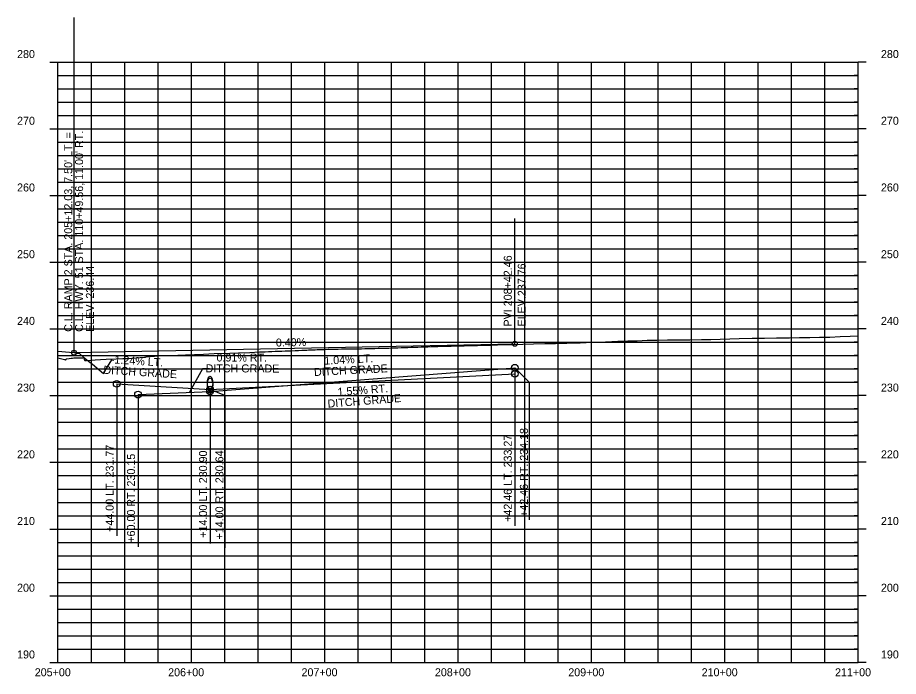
# Model space of a CAD drawing. Extents: x 921603 to 924670, y 1759276 to 1766491.
# Drawn here: x 921610 to 922270, y 1762922 to 1763416 of the extents above; entities that cross this region are included whole.
import ezdxf

# ---------------------------------------------------------------- set-up
doc = ezdxf.new("R2010")
doc.units = 0
for name, color, linetype in [('63', 7, 'Continuous'), ('R_Axis_Annotation', 7, 'Continuous'), ('R_Draft', 7, 'Continuous'), ('R_Exist Surface', 7, 'Continuous'), ('R_Grid', 7, 'Continuous'), ('R_Grid Annot', 7, 'Continuous'), ('R_Grid_Minor', 7, 'Continuous'), ('R_Prop Surface', 7, 'Continuous'), ('R_Proposed Road', 7, 'Continuous'), ('R_Vert Alg', 7, 'Continuous'), ('R_Vert Alg Annot', 7, 'Continuous')]:
    doc.layers.add(name, color=color, linetype=linetype)

msp = doc.modelspace()

# ---------------------------------------------------------------- linework, layer by layer
at = {"layer": 'R_Draft'}
for centre in [(921753.83, 1763141.76), (921753.83, 1763140.46)]:
    msp.add_ellipse(centre, major_axis=(0, 5), ratio=0.4, dxfattribs=at)
at = {"layer": 'R_Exist Surface'}
msp.add_lwpolyline([(921639.83, 1763160.51), (921644.68, 1763159.33), (921645, 1763159.26), (921645.36, 1763159.19), (921645.65, 1763158.97), (921645.88, 1763159.34), (921645.95, 1763159.56), (921646.19, 1763159.88), (921646.28, 1763159.86), (921648.22, 1763160.09), (921649.72, 1763160.32), (921650.62, 1763160.36), (921651.8, 1763160.56), (921658.49, 1763160.49), (921659.04, 1763160.74), (921659.23, 1763160.68), (921659.76, 1763158.74), (921659.84, 1763158.55), (921660.72, 1763158.53), (921661.09, 1763158.55), (921667.79, 1763159.02), (921671.63, 1763159.29), (921675.92, 1763159.58), (921683.41, 1763159.86), (921688.44, 1763160.05), (921692, 1763160.17), (921704.74, 1763161.12), (921705.45, 1763161.19), (921706, 1763161.3), (921715.1, 1763161.98), (921729.56, 1763162.47), (921735.45, 1763162.81), (921748.81, 1763163.25), (921756.86, 1763163.84), (921768.7, 1763164.13), (921775.08, 1763164.43), (921783.58, 1763164.69), (921790.8, 1763165.04), (921795.27, 1763165.18), (921797.75, 1763165.26), (921798.46, 1763165.28), (921800.24, 1763165.36), (921802.73, 1763165.47), (921805.21, 1763165.59), (921806.27, 1763165.64), (921807.7, 1763165.68), (921810.19, 1763165.77), (921812.44, 1763165.85), (921812.67, 1763165.86), (921815.16, 1763165.94), (921817.65, 1763166.03), (921818.25, 1763166.05), (921820.13, 1763166.13), (921822.62, 1763166.24), (921825.1, 1763166.35), (921826.45, 1763166.41), (921827.59, 1763166.46), (921830.08, 1763166.57), (921832.56, 1763166.68), (921834.21, 1763166.75), (921835.05, 1763166.77), (921837.54, 1763166.83), (921840.02, 1763166.89), (921842.51, 1763166.95), (921844.85, 1763167), (921845, 1763167), (921847.48, 1763167.1), (921849.97, 1763167.19), (921852.45, 1763167.29), (921852.7, 1763167.29), (921854.94, 1763167.31), (921857.43, 1763167.32), (921859.91, 1763167.33), (921861.85, 1763167.33), (921862.4, 1763167.35), (921864.89, 1763167.39), (921867.37, 1763167.44), (921869.86, 1763167.48), (921872.35, 1763167.51), (921874.79, 1763167.55), (921874.83, 1763167.55), (921877.32, 1763167.63), (921879.81, 1763167.7), (921882.29, 1763167.78), (921884.78, 1763167.85), (921887.26, 1763167.91), (921888, 1763167.93), (921889.75, 1763167.99), (921892.24, 1763168.07), (921894.72, 1763168.15), (921897.21, 1763168.23), (921898.58, 1763168.27), (921899.7, 1763168.31), (921902.18, 1763168.4), (921904.67, 1763168.48), (921907.16, 1763168.56), (921907.85, 1763168.58), (921909.64, 1763168.66), (921912.13, 1763168.76), (921914.62, 1763168.85), (921914.75, 1763168.86), (921917.1, 1763168.94), (921919.59, 1763169.03), (921921.55, 1763169.1), (921922.07, 1763169.12), (921924.56, 1763169.17), (921927.05, 1763169.23), (921929.53, 1763169.28), (921930.95, 1763169.31), (921932.02, 1763169.35), (921934.51, 1763169.41), (921936.99, 1763169.48), (921939.48, 1763169.55), (921939.65, 1763169.55), (921941.97, 1763169.61), (921944.45, 1763169.68), (921946.6, 1763169.73), (921946.94, 1763169.74), (921949.42, 1763169.8), (921951.91, 1763169.86), (921953.51, 1763169.89), (921954.4, 1763169.91), (921956.88, 1763169.95), (921959.37, 1763170), (921961.86, 1763170.04), (921962.23, 1763170.04), (921964.34, 1763170.12), (921966.83, 1763170.2), (921968.8, 1763170.26), (921969.32, 1763170.28), (921975.23, 1763170.46), (921981.58, 1763170.66), (921988.23, 1763170.87), (921996.22, 1763171.04), (922004.84, 1763171.22), (922012.81, 1763171.4), (922021.44, 1763171.57), (922031.34, 1763171.86), (922040.44, 1763172.26), (922050.25, 1763172.54), (922059.45, 1763172.95), (922067.05, 1763173.27), (922074.08, 1763173.42), (922081.61, 1763173.74), (922088.71, 1763173.88), (922096.81, 1763173.95), (922105.46, 1763174.05), (922113.6, 1763174.12), (922122.2, 1763174.22), (922129.31, 1763174.39), (922136.39, 1763174.67), (922143.55, 1763174.84), (922150.58, 1763175.13), (922160.28, 1763175.2), (922169.42, 1763175.4), (922178.47, 1763175.59), (922188.27, 1763175.66), (922195.65, 1763175.92), (922203.41, 1763175.92), (922210.78, 1763176.18), (922218.55, 1763176.17), (922226.2, 1763176.57), (922233.87, 1763176.74), (922239.83, 1763177.04)], dxfattribs=at)
at = {"layer": 'R_Grid'}
for p, q in [((921639.83, 1762932.26), (921639.83, 1763382.26)), ((921639.83, 1763382.26), (922239.83, 1763382.26)), ((921639.83, 1763382.26), (922239.83, 1763382.26)), ((921739.83, 1762932.26), (921739.83, 1763382.26)), ((921839.83, 1762932.26), (921839.83, 1763382.26)), ((921939.83, 1762932.26), (921939.83, 1763382.26)), ((922039.83, 1762932.26), (922039.83, 1763382.26)), ((922139.83, 1762932.26), (922139.83, 1763382.26)), ((922239.83, 1762932.26), (922239.83, 1763382.26)), ((921639.83, 1763332.26), (922239.83, 1763332.26)), ((921639.83, 1763282.26), (922239.83, 1763282.26)), ((921639.83, 1763232.26), (922239.83, 1763232.26)), ((921639.83, 1763182.26), (922239.83, 1763182.26)), ((921639.83, 1763132.26), (922239.83, 1763132.26)), ((921639.83, 1763082.26), (922239.83, 1763082.26)), ((921639.83, 1763032.26), (922239.83, 1763032.26)), ((921639.83, 1762982.26), (922239.83, 1762982.26)), ((921639.83, 1762932.26), (922239.83, 1762932.26))]:
    msp.add_line(p, q, dxfattribs=at)
at = {"layer": 'R_Grid Annot'}
for p, q in [((921633.83, 1763382.26), (921639.83, 1763382.26)), ((921633.83, 1763382.26), (921639.83, 1763382.26)), ((922245.83, 1763382.26), (922239.83, 1763382.26)), ((922245.83, 1763382.26), (922239.83, 1763382.26)), ((921639.83, 1763372.26), (921642.83, 1763372.26)), ((922239.83, 1763372.26), (922236.83, 1763372.26)), ((921639.83, 1763362.26), (921642.83, 1763362.26)), ((922239.83, 1763362.26), (922236.83, 1763362.26)), ((921639.83, 1763352.26), (921642.83, 1763352.26)), ((922239.83, 1763352.26), (922236.83, 1763352.26)), ((921639.83, 1763342.26), (921642.83, 1763342.26)), ((922239.83, 1763342.26), (922236.83, 1763342.26)), ((921633.83, 1763332.26), (921639.83, 1763332.26)), ((922245.83, 1763332.26), (922239.83, 1763332.26)), ((921639.83, 1763322.26), (921642.83, 1763322.26)), ((922239.83, 1763322.26), (922236.83, 1763322.26)), ((921639.83, 1763312.26), (921642.83, 1763312.26)), ((922239.83, 1763312.26), (922236.83, 1763312.26)), ((921639.83, 1763302.26), (921642.83, 1763302.26)), ((922239.83, 1763302.26), (922236.83, 1763302.26)), ((921639.83, 1763292.26), (921642.83, 1763292.26)), ((922239.83, 1763292.26), (922236.83, 1763292.26)), ((921633.83, 1763282.26), (921639.83, 1763282.26)), ((922245.83, 1763282.26), (922239.83, 1763282.26)), ((921639.83, 1763272.26), (921642.83, 1763272.26)), ((922239.83, 1763272.26), (922236.83, 1763272.26)), ((921639.83, 1763262.26), (921642.83, 1763262.26)), ((922239.83, 1763262.26), (922236.83, 1763262.26)), ((921639.83, 1763252.26), (921642.83, 1763252.26)), ((922239.83, 1763252.26), (922236.83, 1763252.26)), ((921639.83, 1763242.26), (921642.83, 1763242.26)), ((922239.83, 1763242.26), (922236.83, 1763242.26)), ((921633.83, 1763232.26), (921639.83, 1763232.26)), ((922245.83, 1763232.26), (922239.83, 1763232.26)), ((921639.83, 1763222.26), (921642.83, 1763222.26)), ((922239.83, 1763222.26), (922236.83, 1763222.26)), ((921639.83, 1763212.26), (921642.83, 1763212.26)), ((922239.83, 1763212.26), (922236.83, 1763212.26)), ((921639.83, 1763202.26), (921642.83, 1763202.26)), ((922239.83, 1763202.26), (922236.83, 1763202.26)), ((921639.83, 1763192.26), (921642.83, 1763192.26)), ((922239.83, 1763192.26), (922236.83, 1763192.26)), ((921633.83, 1763182.26), (921639.83, 1763182.26)), ((922245.83, 1763182.26), (922239.83, 1763182.26)), ((921639.83, 1763172.26), (921642.83, 1763172.26)), ((922239.83, 1763172.26), (922236.83, 1763172.26)), ((921639.83, 1763162.26), (921642.83, 1763162.26)), ((922239.83, 1763162.26), (922236.83, 1763162.26)), ((921639.83, 1763152.26), (921642.83, 1763152.26)), ((922239.83, 1763152.26), (922236.83, 1763152.26)), ((921639.83, 1763142.26), (921642.83, 1763142.26)), ((922239.83, 1763142.26), (922236.83, 1763142.26)), ((921633.83, 1763132.26), (921639.83, 1763132.26)), ((922245.83, 1763132.26), (922239.83, 1763132.26)), ((921639.83, 1763122.26), (921642.83, 1763122.26)), ((922239.83, 1763122.26), (922236.83, 1763122.26)), ((921639.83, 1763112.26), (921642.83, 1763112.26)), ((922239.83, 1763112.26), (922236.83, 1763112.26)), ((921639.83, 1763102.26), (921642.83, 1763102.26)), ((922239.83, 1763102.26), (922236.83, 1763102.26)), ((921639.83, 1763092.26), (921642.83, 1763092.26)), ((922239.83, 1763092.26), (922236.83, 1763092.26)), ((921633.83, 1763082.26), (921639.83, 1763082.26)), ((922245.83, 1763082.26), (922239.83, 1763082.26)), ((921639.83, 1763072.26), (921642.83, 1763072.26)), ((922239.83, 1763072.26), (922236.83, 1763072.26)), ((921639.83, 1763062.26), (921642.83, 1763062.26)), ((922239.83, 1763062.26), (922236.83, 1763062.26)), ((921639.83, 1763052.26), (921642.83, 1763052.26)), ((922239.83, 1763052.26), (922236.83, 1763052.26)), ((921639.83, 1763042.26), (921642.83, 1763042.26)), ((922239.83, 1763042.26), (922236.83, 1763042.26)), ((921633.83, 1763032.26), (921639.83, 1763032.26)), ((922245.83, 1763032.26), (922239.83, 1763032.26)), ((921639.83, 1763022.26), (921642.83, 1763022.26)), ((922239.83, 1763022.26), (922236.83, 1763022.26)), ((921639.83, 1763012.26), (921642.83, 1763012.26)), ((922239.83, 1763012.26), (922236.83, 1763012.26)), ((921639.83, 1763002.26), (921642.83, 1763002.26)), ((922239.83, 1763002.26), (922236.83, 1763002.26)), ((921639.83, 1762992.26), (921642.83, 1762992.26)), ((922239.83, 1762992.26), (922236.83, 1762992.26)), ((921633.83, 1762982.26), (921639.83, 1762982.26)), ((922245.83, 1762982.26), (922239.83, 1762982.26)), ((921639.83, 1762972.26), (921642.83, 1762972.26)), ((922239.83, 1762972.26), (922236.83, 1762972.26)), ((921639.83, 1762962.26), (921642.83, 1762962.26)), ((922239.83, 1762962.26), (922236.83, 1762962.26)), ((921639.83, 1762952.26), (921642.83, 1762952.26)), ((922239.83, 1762952.26), (922236.83, 1762952.26)), ((921639.83, 1762942.26), (921642.83, 1762942.26)), ((922239.83, 1762942.26), (922236.83, 1762942.26)), ((921633.83, 1762932.26), (921639.83, 1762932.26)), ((922245.83, 1762932.26), (922239.83, 1762932.26))]:
    msp.add_line(p, q, dxfattribs=at)
at = {"layer": 'R_Grid_Minor'}
for p, q in [((921664.83, 1762932.26), (921664.83, 1763382.26)), ((921689.83, 1762932.26), (921689.83, 1763382.26)), ((921714.83, 1762932.26), (921714.83, 1763382.26)), ((921764.83, 1762932.26), (921764.83, 1763382.26)), ((921789.83, 1762932.26), (921789.83, 1763382.26)), ((921814.83, 1762932.26), (921814.83, 1763382.26)), ((921864.83, 1762932.26), (921864.83, 1763382.26)), ((921889.83, 1762932.26), (921889.83, 1763382.26)), ((921914.83, 1762932.26), (921914.83, 1763382.26)), ((921964.83, 1762932.26), (921964.83, 1763382.26)), ((921989.83, 1762932.26), (921989.83, 1763382.26)), ((922014.83, 1762932.26), (922014.83, 1763382.26)), ((922064.83, 1762932.26), (922064.83, 1763382.26)), ((922089.83, 1762932.26), (922089.83, 1763382.26)), ((922114.83, 1762932.26), (922114.83, 1763382.26)), ((922164.83, 1762932.26), (922164.83, 1763382.26)), ((922189.83, 1762932.26), (922189.83, 1763382.26)), ((922214.83, 1762932.26), (922214.83, 1763382.26)), ((921639.83, 1763372.26), (922239.83, 1763372.26)), ((921639.83, 1763362.26), (922239.83, 1763362.26)), ((921639.83, 1763352.26), (922239.83, 1763352.26)), ((921639.83, 1763342.26), (922239.83, 1763342.26)), ((921639.83, 1763322.26), (922239.83, 1763322.26)), ((921639.83, 1763312.26), (922239.83, 1763312.26)), ((921639.83, 1763302.26), (922239.83, 1763302.26)), ((921639.83, 1763292.26), (922239.83, 1763292.26)), ((921639.83, 1763272.26), (922239.83, 1763272.26)), ((921639.83, 1763262.26), (922239.83, 1763262.26)), ((921639.83, 1763252.26), (922239.83, 1763252.26)), ((921639.83, 1763242.26), (922239.83, 1763242.26)), ((921639.83, 1763222.26), (922239.83, 1763222.26)), ((921639.83, 1763212.26), (922239.83, 1763212.26)), ((921639.83, 1763202.26), (922239.83, 1763202.26)), ((921639.83, 1763192.26), (922239.83, 1763192.26)), ((921639.83, 1763172.26), (922239.83, 1763172.26)), ((921639.83, 1763162.26), (922239.83, 1763162.26)), ((921639.83, 1763152.26), (922239.83, 1763152.26)), ((921639.83, 1763142.26), (922239.83, 1763142.26)), ((921639.83, 1763122.26), (922239.83, 1763122.26)), ((921639.83, 1763112.26), (922239.83, 1763112.26)), ((921639.83, 1763102.26), (922239.83, 1763102.26)), ((921639.83, 1763092.26), (922239.83, 1763092.26)), ((921639.83, 1763072.26), (922239.83, 1763072.26)), ((921639.83, 1763062.26), (922239.83, 1763062.26)), ((921639.83, 1763052.26), (922239.83, 1763052.26)), ((921639.83, 1763042.26), (922239.83, 1763042.26)), ((921639.83, 1763022.26), (922239.83, 1763022.26)), ((921639.83, 1763012.26), (922239.83, 1763012.26)), ((921639.83, 1763002.26), (922239.83, 1763002.26)), ((921639.83, 1762992.26), (922239.83, 1762992.26)), ((921639.83, 1762972.26), (922239.83, 1762972.26)), ((921639.83, 1762962.26), (922239.83, 1762962.26)), ((921639.83, 1762952.26), (922239.83, 1762952.26)), ((921639.83, 1762942.26), (922239.83, 1762942.26))]:
    msp.add_line(p, q, dxfattribs=at)
at = {"layer": 'R_Prop Surface'}
msp.add_lwpolyline([(921639.83, 1763165.53), (921648.38, 1763164.77), (921651.86, 1763164.46), (921654.05, 1763164.05), (921655.89, 1763163.7), (921658.82, 1763161.31), (921662.78, 1763158.07), (921665.64, 1763155.74), (921674.03, 1763148.89), (921674.28, 1763149.31), (921675.75, 1763151.75), (921680.21, 1763159.17), (921680.56, 1763159.76)], dxfattribs=at)
at = {"layer": 'R_Proposed Road'}
msp.add_line((921651.86, 1763164.46), (921982.29, 1763171.07), dxfattribs=at)
at = {"layer": 'R_Vert Alg'}
for p, q in [((921651.86, 1763164.46), (921982.29, 1763171.07)), ((921753.83, 1763135.46), (921982.29, 1763153.16)), ((921753.83, 1763136.76), (921982.29, 1763148.61)), ((921683.83, 1763141.11), (921753.83, 1763136.76)), ((921699.83, 1763133.01), (921753.83, 1763135.46))]:
    msp.add_line(p, q, dxfattribs=at)
at = {"layer": 'R_Vert Alg Annot'}
for p, q in [((921651.86, 1763174.46), (921651.86, 1763415.57)), ((921982.29, 1763181.07), (921982.29, 1763265.07)), ((921982.29, 1763171.07), (921982.29, 1763181.07)), ((921651.86, 1763164.46), (921651.86, 1763174.46)), ((921982.29, 1763153.16), (921982.29, 1763123.16)), ((921982.29, 1763153.16), (921993.11, 1763142.26)), ((921982.29, 1763148.61), (921982.29, 1763118.61)), ((921993.11, 1763142.26), (921993.11, 1763112.26)), ((921683.83, 1763141.11), (921683.83, 1763111.11)), ((921753.83, 1763136.76), (921753.83, 1763106.76)), ((921764.83, 1763132.26), (921753.83, 1763136.76)), ((921753.83, 1763135.46), (921753.83, 1763105.46)), ((921699.83, 1763133.01), (921699.83, 1763103.01)), ((921764.83, 1763132.26), (921764.83, 1763102.26)), ((921982.29, 1763123.16), (921982.29, 1763039.16)), ((921993.11, 1763123.16), (921993.11, 1763039.16)), ((921982.29, 1763118.61), (921982.29, 1763034.61)), ((921683.83, 1763111.11), (921683.83, 1763027.11)), ((921699.83, 1763103.01), (921699.83, 1763019.01)), ((921753.83, 1763106.76), (921753.83, 1763022.76)), ((921753.83, 1763105.46), (921753.83, 1763021.46)), ((921764.83, 1763102.26), (921764.83, 1763018.26))]:
    msp.add_line(p, q, dxfattribs=at)
msp.add_lwpolyline([(921753.4, 1763152.26), (921748.29, 1763152.26), (921738.55, 1763134.77)], dxfattribs=at)
for centre, radius in [((921982.29, 1763171.07), 1.85), ((921651.86, 1763164.46), 1.85), ((921982.29, 1763153.16), 2.5), ((921982.29, 1763148.61), 2.5), ((921683.83, 1763141.11), 2.5), ((921699.83, 1763133.01), 2.5), ((921753.83, 1763136.76), 2.5), ((921753.83, 1763135.46), 2.5)]:
    msp.add_circle(centre, radius, dxfattribs=at)

# ---------------------------------------------------------------- texts
at = {"layer": '63'}
msp.add_text('-', height=0.0001, dxfattribs=at).set_placement((921639.83, 1762932.26))
at = {"layer": 'R_Axis_Annotation'}
for s, p in [('280', (921609.16, 1763385.26)), ('280', (921609.16, 1763385.26)), ('280', (922256.84, 1763385.26)), ('280', (922256.84, 1763385.26)), ('270', (921609.16, 1763335.26)), ('270', (922256.84, 1763335.26)), ('260', (921609.16, 1763285.26)), ('260', (922256.84, 1763285.26)), ('250', (921609.16, 1763235.26)), ('250', (922256.84, 1763235.26)), ('240', (921609.16, 1763185.26)), ('240', (922256.84, 1763185.26)), ('230', (921609.16, 1763135.26)), ('230', (922256.84, 1763135.26)), ('220', (921609.16, 1763085.26)), ('220', (922256.84, 1763085.26)), ('210', (921609.16, 1763035.26)), ('210', (922256.84, 1763035.26)), ('200', (921609.16, 1762985.26)), ('200', (922256.84, 1762985.26)), ('190', (921609.16, 1762935.26)), ('190', (922256.84, 1762935.26)), ('205+00', (921622.42, 1762921.91)), ('206+00', (921722.42, 1762921.91)), ('207+00', (921822.42, 1762921.91)), ('208+00', (921922.42, 1762921.91)), ('209+00', (922022.42, 1762921.91)), ('210+00', (922122.42, 1762921.91)), ('211+00', (922222.42, 1762921.91))]:
    msp.add_text(s, height=6, dxfattribs=at).set_placement(p)
at = {"layer": 'R_Vert Alg Annot'}
for s, rotation, p in [("C.L. RAMP 2 STA. 205+12.03, 7.50' LT. =", 90, (921650.51, 1763180.05)), ("C.L. HWY. 51 STA. 110+49.56, 11.00' RT.", 90, (921658.64, 1763180.05)), ('PVI 208+42.46', 90, (921980.04, 1763184.07)), ('ELEV. 236.44', 90, (921666.76, 1763180.05)), ('ELEV.237.76', 90, (921990.54, 1763184.07)), ('0.40%', 1.14576, (921803.25, 1763168.99)), ('-1.24% LT.', 356.44405, (921679.36, 1763156.49)), ('0.91% RT.', 359.80967, (921758.68, 1763157.84)), ('1.04% LT.', 2.96922, (921839.65, 1763155.44)), (' DITCH GRADE', 356.44405, (921671.49, 1763148.83)), (' DITCH GRADE', 359.80967, (921748.28, 1763149.75)), (' DITCH GRADE', 2.96922, (921829.7, 1763146.79)), ('1.55% RT.', 4.43016, (921849.68, 1763131.94)), (' DITCH GRADE', 4.43016, (921839.96, 1763123.04)), ('+42.46 LT. 233.27', 90, (921980.04, 1763037.61)), ('+42.46 RT. 234.18', 90, (921992.15, 1763041.31)), ('+44.00 LT. 231.77', 90, (921681.58, 1763030.11)), ('+14.00 LT. 230.90', 90, (921751.58, 1763025.76)), ('+14.00 RT. 230.64', 90, (921763.86, 1763024.46)), ('+60.00 RT. 230.15', 90, (921697.58, 1763022.01))]:
    msp.add_text(s, height=6, rotation=rotation, dxfattribs=at).set_placement(p)

doc.saveas('drawing.dxf')
